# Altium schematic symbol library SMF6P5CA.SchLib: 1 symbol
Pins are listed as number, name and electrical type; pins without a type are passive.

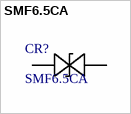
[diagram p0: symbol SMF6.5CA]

## SMF6.5CA
designator CR?
Description; Manufacturer_Name: Littelfuse Inc
footprint SOD-123F_LTF
pins: 1, 2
